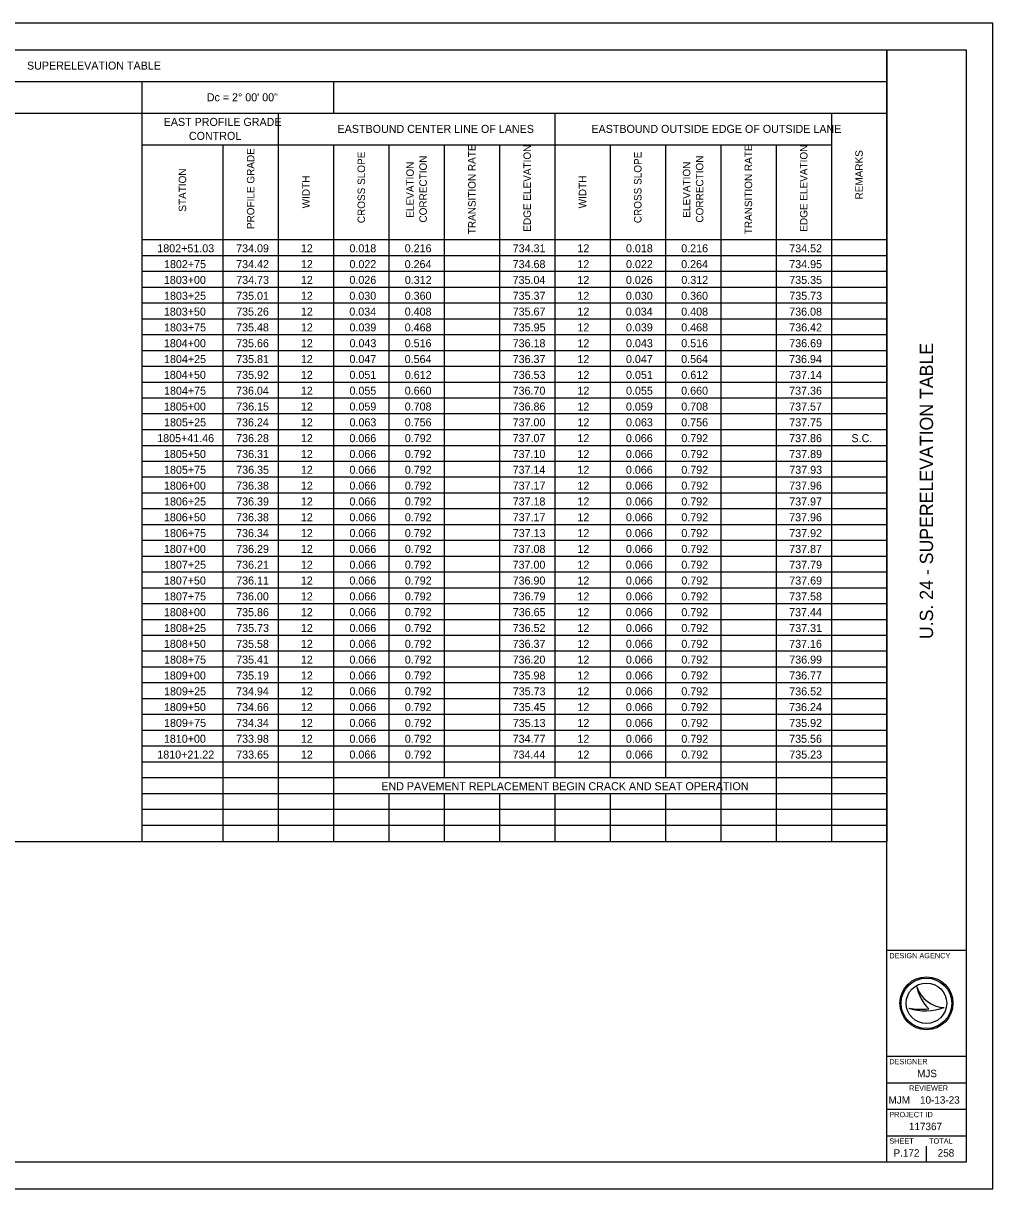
# Model space of a CAD drawing. Extents: x -38.9 to 34, y 0 to 22.
# Drawn here: x 15.71 to 34, y 0 to 22 of the extents above; entities that cross this region are included whole.
import ezdxf

# ---------------------------------------------------------------- set-up
doc = ezdxf.new("R2010")
doc.units = 0
for name, color, linetype in [('SH_Border', 7, 'Continuous'), ('SH_Cut_Line', 7, 'Continuous'), ('SH_Data', 7, 'Continuous'), ('SH_Text', 7, 'Continuous')]:
    doc.layers.add(name, color=color, linetype=linetype)

msp = doc.modelspace()

# ---------------------------------------------------------------- linework, layer by layer
at = {"layer": 'SH_Border'}
for p, q in [((32, 0.5), (32, 21.5)), ((32, 4.5), (33.5, 4.5)), ((32, 2.5), (33.5, 2.5)), ((32, 2), (33.5, 2)), ((32, 1.5), (33.5, 1.5)), ((32, 1), (33.5, 1))]:
    msp.add_line(p, q, dxfattribs=at)
msp.add_lwpolyline([(1.5, 21.5), (33.5, 21.5), (33.5, 0.5), (1.5, 0.5)], close=True, dxfattribs=at)
at = {"layer": 'SH_Cut_Line'}
msp.add_lwpolyline([(0, 0), (34, 0), (34, 22), (0, 22)], close=True, dxfattribs=at)
at = {"layer": 'SH_Data'}
for p, q in [((32.567, 3.81), (32.567, 3.81)), ((32.417, 3.41), (32.417, 3.41)), ((32.75, 3.5), (32.75, 3.5)), ((33.087, 3.419), (33.087, 3.419)), ((32.375, 0.675), (32.375, 0.675)), ((32.75, 0.5), (32.75, 0.8))]:
    msp.add_line(p, q, dxfattribs=at)
for radius in [0.5, 0.477, 0.477, 0.382]:
    msp.add_circle((32.75, 3.5), radius, dxfattribs=at)
for centre, radius, start, end in [((33.116, 3.998), 0.58, 198.9257, 198.9319), ((33.347, 3.97), 0.796, 191.6379, 191.6421), ((33.116, 3.998), 0.58, 198.9319, 267.1657), ((33.347, 3.97), 0.796, 191.6421, 226.0947), ((32.739, 4.37), 1.013, 251.4576, 290.0832), ((32.648, 4.654), 1.266, 259.4964, 259.4995), ((32.739, 4.37), 1.013, 251.4527, 251.4576), ((32.648, 4.654), 1.266, 259.4995, 276.6672)]:
    msp.add_arc(centre, radius, start, end, dxfattribs=at)
at = {"layer": 'SH_Text'}
for p, q in [((1.5, 21.5), (32, 21.5)), ((32, 21.5), (32, 6.552)), ((1.5, 20.903), (32, 20.903)), ((17.947, 20.903), (17.947, 6.552)), ((21.564, 20.903), (21.564, 20.305)), ((1.5, 20.305), (32, 20.305)), ((20.521, 20.305), (20.521, 17.916)), ((25.739, 20.305), (25.739, 17.916)), ((30.956, 20.305), (30.956, 17.916)), ((17.947, 19.708), (30.956, 19.708)), ((19.477, 19.708), (19.477, 17.916)), ((21.564, 19.708), (21.564, 17.916)), ((22.608, 19.708), (22.608, 17.916)), ((23.651, 19.708), (23.651, 17.916)), ((24.695, 19.708), (24.695, 17.916)), ((26.782, 19.708), (26.782, 17.916)), ((27.826, 19.708), (27.826, 17.916)), ((28.869, 19.708), (28.869, 17.916)), ((29.913, 19.708), (29.913, 17.916)), ((17.947, 17.916), (32, 17.916)), ((19.477, 17.916), (19.477, 6.552)), ((20.521, 17.916), (20.521, 6.552)), ((21.564, 17.916), (21.564, 6.552)), ((22.608, 17.916), (22.608, 7.761)), ((23.651, 17.916), (23.651, 7.761)), ((24.695, 17.916), (24.695, 7.761)), ((25.739, 17.916), (25.739, 7.761)), ((26.782, 17.916), (26.782, 7.761)), ((27.826, 17.916), (27.826, 7.761)), ((28.869, 17.916), (28.869, 6.552)), ((29.913, 17.916), (29.913, 6.552)), ((30.956, 17.916), (30.956, 6.552)), ((17.947, 17.617), (32, 17.617)), ((17.947, 17.319), (32, 17.319)), ((17.947, 17.02), (32, 17.02)), ((17.947, 16.721), (32, 16.721)), ((17.947, 16.423), (32, 16.423)), ((17.947, 16.124), (32, 16.124)), ((17.947, 15.825), (32, 15.825)), ((17.947, 15.527), (32, 15.527)), ((17.947, 15.228), (32, 15.228)), ((17.947, 14.929), (32, 14.929)), ((17.947, 14.631), (32, 14.631)), ((17.947, 14.332), (32, 14.332)), ((17.947, 14.033), (32, 14.033)), ((17.947, 13.735), (32, 13.735)), ((17.947, 13.436), (32, 13.436)), ((17.947, 13.137), (32, 13.137)), ((17.947, 12.839), (32, 12.839)), ((17.947, 12.54), (32, 12.54)), ((17.947, 12.241), (32, 12.241)), ((17.947, 11.943), (32, 11.943)), ((17.947, 11.644), (32, 11.644)), ((17.947, 11.345), (32, 11.345)), ((17.947, 11.047), (32, 11.047)), ((17.947, 10.748), (32, 10.748)), ((17.947, 10.449), (32, 10.449)), ((17.947, 10.151), (32, 10.151)), ((17.947, 9.852), (32, 9.852)), ((17.947, 9.553), (32, 9.553)), ((17.947, 9.255), (32, 9.255)), ((17.947, 8.956), (32, 8.956)), ((17.947, 8.657), (32, 8.657)), ((17.947, 8.359), (32, 8.359)), ((17.947, 8.06), (32, 8.06)), ((17.947, 7.761), (32, 7.761)), ((17.947, 7.463), (32, 7.463)), ((22.608, 7.463), (22.608, 6.552)), ((23.651, 7.463), (23.651, 6.552)), ((24.695, 7.463), (24.695, 6.552)), ((25.739, 7.463), (25.739, 6.552)), ((26.782, 7.463), (26.782, 6.552)), ((27.826, 7.463), (27.826, 6.552)), ((17.947, 7.164), (32, 7.164)), ((17.947, 6.865), (32, 6.865)), ((1.5, 6.552), (32, 6.552))]:
    msp.add_line(p, q, dxfattribs=at)

# ---------------------------------------------------------------- texts
at = {"layer": 'SH_Data'}
msp.add_text('U.S. 24 - SUPERELEVATION TABLE', height=0.25, rotation=90, dxfattribs=at).set_placement((32.875, 10.375))
for s, height, p in [('DESIGN AGENCY', 0.1, (32.05, 4.35)), ('DESIGNER', 0.1, (32.05, 2.35)), ('MJS', 0.14, (32.574, 2.105)), ('REVIEWER', 0.1, (32.422, 1.85)), ('MJM', 0.14, (32.035, 1.605)), ('10-13-23', 0.14, (32.629, 1.605)), ('PROJECT ID', 0.1, (32.05, 1.35)), ('117367', 0.14, (32.42, 1.105)), ('SHEET', 0.1, (32.05, 0.85)), ('TOTAL', 0.1, (32.8, 0.85)), ('P.172', 0.14, (32.129, 0.605)), ('258', 0.14, (32.962, 0.605))]:
    msp.add_text(s, height=height, dxfattribs=at).set_placement(p)
at = {"layer": 'SH_Text'}
for s, height, p in [('SUPERELEVATION TABLE', 0.15112, (15.779, 21.126)), ('Dc = 2° 00\' 00"', 0.15112, (19.171, 20.528)), ('EAST PROFILE GRADE ', 0.15112, (18.358, 20.063)), ('EASTBOUND CENTER LINE OF LANES', 0.15112, (21.639, 19.931)), ('EASTBOUND OUTSIDE EDGE OF OUTSIDE LANE', 0.15112, (26.429, 19.931)), ('CONTROL', 0.1511, (18.834, 19.799)), ('1802+51.03', 0.1511, (18.238, 17.677)), ('734.09', 0.1511, (19.726, 17.677)), ('12', 0.1511, (20.947, 17.677)), ('0.018', 0.1511, (21.863, 17.677)), ('0.216', 0.1511, (22.906, 17.677)), ('734.31', 0.1511, (24.944, 17.677)), ('12', 0.1511, (26.165, 17.677)), ('0.018', 0.1511, (27.081, 17.677)), ('0.216', 0.1511, (28.124, 17.677)), ('734.52', 0.1511, (30.162, 17.677)), ('1802+75', 0.1511, (18.365, 17.378)), ('734.42', 0.1511, (19.726, 17.378)), ('12', 0.1511, (20.947, 17.378)), ('0.022', 0.1511, (21.864, 17.378)), ('0.264', 0.1511, (22.905, 17.378)), ('734.68', 0.1511, (24.943, 17.378)), ('12', 0.1511, (26.165, 17.378)), ('0.022', 0.1511, (27.082, 17.378)), ('0.264', 0.1511, (28.123, 17.378)), ('734.95', 0.1511, (30.162, 17.378)), ('1803+00', 0.1511, (18.362, 17.08)), ('734.73', 0.1511, (19.727, 17.08)), ('12', 0.1511, (20.947, 17.08)), ('0.026', 0.1511, (21.863, 17.08)), ('0.312', 0.1511, (22.908, 17.08)), ('735.04', 0.1511, (24.942, 17.08)), ('12', 0.1511, (26.165, 17.08)), ('0.026', 0.1511, (27.08, 17.08)), ('0.312', 0.1511, (28.126, 17.08)), ('735.35', 0.1511, (30.162, 17.08)), ('1803+25', 0.1511, (18.365, 16.781)), ('735.01', 0.1511, (19.726, 16.781)), ('12', 0.1511, (20.947, 16.781)), ('0.030', 0.1511, (21.862, 16.781)), ('0.360', 0.1511, (22.906, 16.781)), ('735.37', 0.1511, (24.943, 16.781)), ('12', 0.1511, (26.165, 16.781)), ('0.030', 0.1511, (27.08, 16.781)), ('0.360', 0.1511, (28.123, 16.781)), ('735.73', 0.1511, (30.163, 16.781)), ('1803+50', 0.1511, (18.362, 16.482)), ('735.26', 0.1511, (19.725, 16.482)), ('12', 0.1511, (20.947, 16.482)), ('0.034', 0.1511, (21.861, 16.482)), ('0.408', 0.1511, (22.906, 16.482)), ('735.67', 0.1511, (24.943, 16.482)), ('12', 0.1511, (26.165, 16.482)), ('0.034', 0.1511, (27.079, 16.482)), ('0.408', 0.1511, (28.124, 16.482)), ('736.08', 0.1511, (30.161, 16.482)), ('1803+75', 0.1511, (18.365, 16.184)), ('735.48', 0.1511, (19.725, 16.184)), ('12', 0.1511, (20.947, 16.184)), ('0.039', 0.1511, (21.864, 16.184)), ('0.468', 0.1511, (22.906, 16.184)), ('735.95', 0.1511, (24.945, 16.184)), ('12', 0.1511, (26.165, 16.184)), ('0.039', 0.1511, (27.081, 16.184)), ('0.468', 0.1511, (28.124, 16.184)), ('736.42', 0.1511, (30.162, 16.184)), ('1804+00', 0.1511, (18.362, 15.885)), ('735.66', 0.1511, (19.725, 15.885)), ('12', 0.1511, (20.947, 15.885)), ('0.043', 0.1511, (21.865, 15.885)), ('0.516', 0.1511, (22.906, 15.885)), ('736.18', 0.1511, (24.943, 15.885)), ('12', 0.1511, (26.165, 15.885)), ('0.043', 0.1511, (27.082, 15.885)), ('0.516', 0.1511, (28.124, 15.885)), ('736.69', 0.1511, (30.162, 15.885)), ('1804+25', 0.1511, (18.365, 15.586)), ('735.81', 0.1511, (19.726, 15.586)), ('12', 0.1511, (20.947, 15.586)), ('0.047', 0.1511, (21.863, 15.586)), ('0.564', 0.1511, (22.905, 15.586)), ('736.37', 0.1511, (24.943, 15.586)), ('12', 0.1511, (26.165, 15.586)), ('0.047', 0.1511, (27.081, 15.586)), ('0.564', 0.1511, (28.123, 15.586)), ('736.94', 0.1511, (30.159, 15.586)), ('1804+50', 0.1511, (18.362, 15.288)), ('735.92', 0.1511, (19.726, 15.288)), ('12', 0.1511, (20.947, 15.288)), ('0.051', 0.1511, (21.864, 15.288)), ('0.612', 0.1511, (22.908, 15.288)), ('736.53', 0.1511, (24.945, 15.288)), ('12', 0.1511, (26.165, 15.288)), ('0.051', 0.1511, (27.082, 15.288)), ('0.612', 0.1511, (28.126, 15.288)), ('737.14', 0.1511, (30.159, 15.288)), ('1804+75', 0.1511, (18.365, 14.989)), ('736.04', 0.1511, (19.724, 14.989)), ('12', 0.1511, (20.947, 14.989)), ('0.055', 0.1511, (21.864, 14.989)), ('0.660', 0.1511, (22.906, 14.989)), ('736.70', 0.1511, (24.942, 14.989)), ('12', 0.1511, (26.165, 14.989)), ('0.055', 0.1511, (27.082, 14.989)), ('0.660', 0.1511, (28.123, 14.989)), ('737.36', 0.1511, (30.16, 14.989)), ('1805+00', 0.1511, (18.362, 14.69)), ('736.15', 0.1511, (19.727, 14.69)), ('12', 0.1511, (20.947, 14.69)), ('0.059', 0.1511, (21.864, 14.69)), ('0.708', 0.1511, (22.906, 14.69)), ('736.86', 0.1511, (24.943, 14.69)), ('12', 0.1511, (26.165, 14.69)), ('0.059', 0.1511, (27.081, 14.69)), ('0.708', 0.1511, (28.124, 14.69)), ('737.57', 0.1511, (30.161, 14.69)), ('1805+25', 0.1511, (18.365, 14.392)), ('736.24', 0.1511, (19.724, 14.392)), ('12', 0.1511, (20.947, 14.392)), ('0.063', 0.1511, (21.865, 14.392)), ('0.756', 0.1511, (22.906, 14.392)), ('737.00', 0.1511, (24.942, 14.392)), ('12', 0.1511, (26.165, 14.392)), ('0.063', 0.1511, (27.082, 14.392)), ('0.756', 0.1511, (28.124, 14.392)), ('737.75', 0.1511, (30.162, 14.392)), ('1805+41.46', 0.1511, (18.236, 14.093)), ('736.28', 0.1511, (19.725, 14.093)), ('12', 0.1511, (20.947, 14.093)), ('0.066', 0.1511, (21.863, 14.093)), ('0.792', 0.1511, (22.908, 14.093)), ('737.07', 0.1511, (24.943, 14.093)), ('12', 0.1511, (26.165, 14.093)), ('0.066', 0.1511, (27.08, 14.093)), ('0.792', 0.1511, (28.126, 14.093)), ('737.86', 0.1511, (30.16, 14.093)), ('S.C.', 0.1511, (31.336, 14.093)), ('1805+50', 0.1511, (18.362, 13.794)), ('736.31', 0.1511, (19.726, 13.794)), ('12', 0.1511, (20.947, 13.794)), ('0.066', 0.1511, (21.863, 13.794)), ('0.792', 0.1511, (22.908, 13.794)), ('737.10', 0.1511, (24.942, 13.794)), ('12', 0.1511, (26.165, 13.794)), ('0.066', 0.1511, (27.08, 13.794)), ('0.792', 0.1511, (28.126, 13.794)), ('737.89', 0.1511, (30.162, 13.794)), ('1805+75', 0.1511, (18.365, 13.496)), ('736.35', 0.1511, (19.727, 13.496)), ('12', 0.1511, (20.947, 13.496)), ('0.066', 0.1511, (21.863, 13.496)), ('0.792', 0.1511, (22.908, 13.496)), ('737.14', 0.1511, (24.942, 13.496)), ('12', 0.1511, (26.165, 13.496)), ('0.066', 0.1511, (27.08, 13.496)), ('0.792', 0.1511, (28.126, 13.496)), ('737.93', 0.1511, (30.163, 13.496)), ('1806+00', 0.1511, (18.362, 13.197)), ('736.38', 0.1511, (19.725, 13.197)), ('12', 0.1511, (20.947, 13.197)), ('0.066', 0.1511, (21.863, 13.197)), ('0.792', 0.1511, (22.908, 13.197)), ('737.17', 0.1511, (24.943, 13.197)), ('12', 0.1511, (26.165, 13.197)), ('0.066', 0.1511, (27.08, 13.197)), ('0.792', 0.1511, (28.126, 13.197)), ('737.96', 0.1511, (30.16, 13.197)), ('1806+25', 0.1511, (18.365, 12.898)), ('736.39', 0.1511, (19.726, 12.898)), ('12', 0.1511, (20.947, 12.898)), ('0.066', 0.1511, (21.863, 12.898)), ('0.792', 0.1511, (22.908, 12.898)), ('737.18', 0.1511, (24.943, 12.898)), ('12', 0.1511, (26.165, 12.898)), ('0.066', 0.1511, (27.08, 12.898)), ('0.792', 0.1511, (28.126, 12.898)), ('737.97', 0.1511, (30.161, 12.898)), ('1806+50', 0.1511, (18.362, 12.6)), ('736.38', 0.1511, (19.725, 12.6)), ('12', 0.1511, (20.947, 12.6)), ('0.066', 0.1511, (21.863, 12.6)), ('0.792', 0.1511, (22.908, 12.6)), ('737.17', 0.1511, (24.943, 12.6)), ('12', 0.1511, (26.165, 12.6)), ('0.066', 0.1511, (27.08, 12.6)), ('0.792', 0.1511, (28.126, 12.6)), ('737.96', 0.1511, (30.16, 12.6)), ('1806+75', 0.1511, (18.365, 12.301)), ('736.34', 0.1511, (19.724, 12.301)), ('12', 0.1511, (20.947, 12.301)), ('0.066', 0.1511, (21.863, 12.301)), ('0.792', 0.1511, (22.908, 12.301)), ('737.13', 0.1511, (24.945, 12.301)), ('12', 0.1511, (26.165, 12.301)), ('0.066', 0.1511, (27.08, 12.301)), ('0.792', 0.1511, (28.126, 12.301)), ('737.92', 0.1511, (30.162, 12.301)), ('1807+00', 0.1511, (18.362, 12.002)), ('736.29', 0.1511, (19.726, 12.002)), ('12', 0.1511, (20.947, 12.002)), ('0.066', 0.1511, (21.863, 12.002)), ('0.792', 0.1511, (22.908, 12.002)), ('737.08', 0.1511, (24.943, 12.002)), ('12', 0.1511, (26.165, 12.002)), ('0.066', 0.1511, (27.08, 12.002)), ('0.792', 0.1511, (28.126, 12.002)), ('737.87', 0.1511, (30.161, 12.002)), ('1807+25', 0.1511, (18.365, 11.704)), ('736.21', 0.1511, (19.726, 11.704)), ('12', 0.1511, (20.947, 11.704)), ('0.066', 0.1511, (21.863, 11.704)), ('0.792', 0.1511, (22.908, 11.704)), ('737.00', 0.1511, (24.942, 11.704)), ('12', 0.1511, (26.165, 11.704)), ('0.066', 0.1511, (27.08, 11.704)), ('0.792', 0.1511, (28.126, 11.704)), ('737.79', 0.1511, (30.162, 11.704)), ('1807+50', 0.1511, (18.362, 11.405)), ('736.11', 0.1511, (19.726, 11.405)), ('12', 0.1511, (20.947, 11.405)), ('0.066', 0.1511, (21.863, 11.405)), ('0.792', 0.1511, (22.908, 11.405)), ('736.90', 0.1511, (24.942, 11.405)), ('12', 0.1511, (26.165, 11.405)), ('0.066', 0.1511, (27.08, 11.405)), ('0.792', 0.1511, (28.126, 11.405)), ('737.69', 0.1511, (30.162, 11.405)), ('1807+75', 0.1511, (18.365, 11.106)), ('736.00', 0.1511, (19.724, 11.106)), ('12', 0.1511, (20.947, 11.106)), ('0.066', 0.1511, (21.863, 11.106)), ('0.792', 0.1511, (22.908, 11.106)), ('736.79', 0.1511, (24.944, 11.106)), ('12', 0.1511, (26.165, 11.106)), ('0.066', 0.1511, (27.08, 11.106)), ('0.792', 0.1511, (28.126, 11.106)), ('737.58', 0.1511, (30.161, 11.106)), ('1808+00', 0.1511, (18.362, 10.808)), ('735.86', 0.1511, (19.725, 10.808)), ('12', 0.1511, (20.947, 10.808)), ('0.066', 0.1511, (21.863, 10.808)), ('0.792', 0.1511, (22.908, 10.808)), ('736.65', 0.1511, (24.945, 10.808)), ('12', 0.1511, (26.165, 10.808)), ('0.066', 0.1511, (27.08, 10.808)), ('0.792', 0.1511, (28.126, 10.808)), ('737.44', 0.1511, (30.159, 10.808)), ('1808+25', 0.1511, (18.365, 10.509)), ('735.73', 0.1511, (19.727, 10.509)), ('12', 0.1511, (20.947, 10.509)), ('0.066', 0.1511, (21.863, 10.509)), ('0.792', 0.1511, (22.908, 10.509)), ('736.52', 0.1511, (24.944, 10.509)), ('12', 0.1511, (26.165, 10.509)), ('0.066', 0.1511, (27.08, 10.509)), ('0.792', 0.1511, (28.126, 10.509)), ('737.31', 0.1511, (30.162, 10.509)), ('1808+50', 0.1511, (18.362, 10.21)), ('735.58', 0.1511, (19.725, 10.21)), ('12', 0.1511, (20.947, 10.21)), ('0.066', 0.1511, (21.863, 10.21)), ('0.792', 0.1511, (22.908, 10.21)), ('736.37', 0.1511, (24.943, 10.21)), ('12', 0.1511, (26.165, 10.21)), ('0.066', 0.1511, (27.08, 10.21)), ('0.792', 0.1511, (28.126, 10.21)), ('737.16', 0.1511, (30.16, 10.21)), ('1808+75', 0.1511, (18.365, 9.912)), ('735.41', 0.1511, (19.726, 9.912)), ('12', 0.1511, (20.947, 9.912)), ('0.066', 0.1511, (21.863, 9.912)), ('0.792', 0.1511, (22.908, 9.912)), ('736.20', 0.1511, (24.942, 9.912)), ('12', 0.1511, (26.165, 9.912)), ('0.066', 0.1511, (27.08, 9.912)), ('0.792', 0.1511, (28.126, 9.912)), ('736.99', 0.1511, (30.162, 9.912)), ('1809+00', 0.1511, (18.362, 9.613)), ('735.19', 0.1511, (19.726, 9.613)), ('12', 0.1511, (20.947, 9.613)), ('0.066', 0.1511, (21.863, 9.613)), ('0.792', 0.1511, (22.908, 9.613)), ('735.98', 0.1511, (24.943, 9.613)), ('12', 0.1511, (26.165, 9.613)), ('0.066', 0.1511, (27.08, 9.613)), ('0.792', 0.1511, (28.126, 9.613)), ('736.77', 0.1511, (30.161, 9.613)), ('1809+25', 0.1511, (18.365, 9.314)), ('734.94', 0.1511, (19.724, 9.314)), ('12', 0.1511, (20.947, 9.314)), ('0.066', 0.1511, (21.863, 9.314)), ('0.792', 0.1511, (22.908, 9.314)), ('735.73', 0.1511, (24.945, 9.314)), ('12', 0.1511, (26.165, 9.314)), ('0.066', 0.1511, (27.08, 9.314)), ('0.792', 0.1511, (28.126, 9.314)), ('736.52', 0.1511, (30.162, 9.314)), ('1809+50', 0.1511, (18.362, 9.016)), ('734.66', 0.1511, (19.725, 9.016)), ('12', 0.1511, (20.947, 9.016)), ('0.066', 0.1511, (21.863, 9.016)), ('0.792', 0.1511, (22.908, 9.016)), ('735.45', 0.1511, (24.945, 9.016)), ('12', 0.1511, (26.165, 9.016)), ('0.066', 0.1511, (27.08, 9.016)), ('0.792', 0.1511, (28.126, 9.016)), ('736.24', 0.1511, (30.159, 9.016)), ('1809+75', 0.1511, (18.365, 8.717)), ('734.34', 0.1511, (19.724, 8.717)), ('12', 0.1511, (20.947, 8.717)), ('0.066', 0.1511, (21.863, 8.717)), ('0.792', 0.1511, (22.908, 8.717)), ('735.13', 0.1511, (24.945, 8.717)), ('12', 0.1511, (26.165, 8.717)), ('0.066', 0.1511, (27.08, 8.717)), ('0.792', 0.1511, (28.126, 8.717)), ('735.92', 0.1511, (30.162, 8.717)), ('1810+00', 0.1511, (18.362, 8.418)), ('733.98', 0.1511, (19.725, 8.418)), ('12', 0.1511, (20.947, 8.418)), ('0.066', 0.1511, (21.863, 8.418)), ('0.792', 0.1511, (22.908, 8.418)), ('734.77', 0.1511, (24.943, 8.418)), ('12', 0.1511, (26.165, 8.418)), ('0.066', 0.1511, (27.08, 8.418)), ('0.792', 0.1511, (28.126, 8.418)), ('735.56', 0.1511, (30.16, 8.418)), ('1810+21.22', 0.1511, (18.238, 8.12)), ('733.65', 0.1511, (19.727, 8.12)), ('12', 0.1511, (20.947, 8.12)), ('0.066', 0.1511, (21.863, 8.12)), ('0.792', 0.1511, (22.908, 8.12)), ('734.44', 0.1511, (24.942, 8.12)), ('12', 0.1511, (26.165, 8.12)), ('0.066', 0.1511, (27.08, 8.12)), ('0.792', 0.1511, (28.126, 8.12)), ('735.23', 0.1511, (30.163, 8.12)), ('END PAVEMENT REPLACEMENT BEGIN CRACK AND SEAT OPERATION', 0.15112, (22.465, 7.522))]:
    msp.add_text(s, height=height, dxfattribs=at).set_placement(p)
for s, height, p in [('PROFILE GRADE', 0.14081, (20.069, 18.115)), ('TRANSITION RATE', 0.14081, (24.244, 18.018)), ('EDGE ELEVATION', 0.14081, (25.287, 18.066)), ('TRANSITION RATE', 0.14081, (29.461, 18.018)), ('EDGE ELEVATION', 0.14081, (30.505, 18.066)), ('REMARKS', 0.1408, (31.549, 18.674)), ('CROSS SLOPE', 0.14081, (22.157, 18.227)), ('ELEVATION ', 0.1408, (23.077, 18.331)), ('CORRECTION', 0.1408, (23.323, 18.238)), ('CROSS SLOPE', 0.14081, (27.374, 18.227)), ('ELEVATION ', 0.1408, (28.295, 18.331)), ('CORRECTION', 0.1408, (28.541, 18.238)), ('STATION', 0.1408, (18.782, 18.444)), ('WIDTH', 0.1408, (21.113, 18.507)), ('WIDTH', 0.1408, (26.331, 18.507))]:
    msp.add_text(s, height=height, rotation=90, dxfattribs=at).set_placement(p)

doc.saveas('drawing.dxf')
